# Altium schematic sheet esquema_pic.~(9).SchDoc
size A4
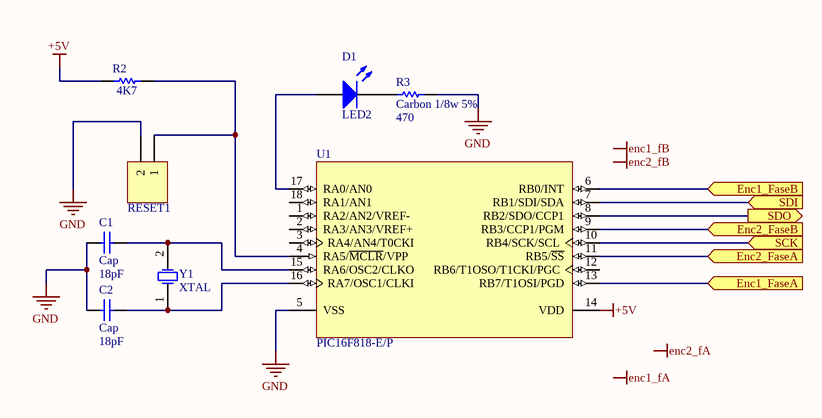
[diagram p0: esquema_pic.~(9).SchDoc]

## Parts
C1  Cap  value 18pF  [RAD-0.3]
C2  Cap  value 18pF  [RAD-0.3]
D1  LED2  [3.2X1.6X1.1]
R2  value 4K7  [1005[0402]]  (hidden comment: Carbon 1/8w 5%)
R3  Carbon 1/8w 5%  value 470  [1005[0402]]
RESET1  Header 2  [HDR1X2]  (value not drawn)
U1  PIC16F818-E/P  [PDIP300-18]
Y1  XTAL  [R38]

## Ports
Enc1_FaseA (in), Enc1_FaseB (in), Enc2_FaseA (in), Enc2_FaseB (in), SCK (in), SDI (in), SDO (out)

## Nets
+5V: R2.1 U1.14(VDD)
GND: C1.1 C2.1 R3.2 RESET1.2 U1.5(VSS)
Enc1_FaseA: U1.13(RB7/T1OSI/PGD) ; port Enc1_FaseA
Enc1_FaseB: U1.6(RB0/INT) ; port Enc1_FaseB
Enc2_FaseA: U1.11(RB5/~{SS}) ; port Enc2_FaseA
Enc2_FaseB: U1.9(RB3/CCP1/PGM) ; port Enc2_FaseB
SCK: U1.10(RB4/SCK/SCL) ; port SCK
SDI: U1.7(RB1/SDI/SDA) ; port SDI
SDO: U1.8(RB2/SDO/CCP1) ; port SDO
NetC1_2: C1.2 U1.15(RA6/OSC2/CLKO) Y1.2(OSC2)
NetC2_2: C2.2 U1.16(RA7/OSC1/CLKI) Y1.1(OSC1)
NetD1_1: D1.1(A) U1.17(RA0/AN0)
NetD1_2: D1.2(K) R3.1
NetR2_2: R2.2 RESET1.1 U1.4(RA5/~{MCLR}/VPP)

Not connected (* = marked no-connect by the designer): U1 1(RA2/AN2/VREF-) 2(RA3/AN3/VREF+) 3(RA4/AN4/T0CKI) 12(RB6/T1OSO/T1CKI/PGC) 18(RA1/AN1)

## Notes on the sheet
- Labels drawn without touching a wire or pin: enc1_fA, enc1_fB, enc2_fA, enc2_fB

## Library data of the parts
C1 C2 = Cap: Capacitor
D1 = LED2: Typical RED, GREEN, YELLOW, AMBER GaAs LED
R2 R3 = Res Semi: Semiconductor Resistor
RESET1 = Header 2: Header, 2-Pin
U1 = PIC16F818-E/P: Enhanced FLASH Microcontroller with nanoWatt Technology, 1K (x14-Bit words) FLASH, 128 Bytes RAM, 18-Pin PDIP, Standard VDD Range, Extended Temperature
Y1 = XTAL: Crystal Oscillator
